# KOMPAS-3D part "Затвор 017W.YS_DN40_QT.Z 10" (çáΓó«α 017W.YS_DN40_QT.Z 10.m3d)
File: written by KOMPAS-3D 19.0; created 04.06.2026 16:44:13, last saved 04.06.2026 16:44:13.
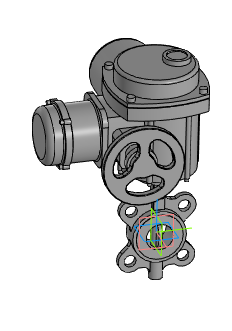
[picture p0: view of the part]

Document properties: Автор: Энергия; Полное имя файла: ..\..\..\3d для проектировщиков\017W разные\x.x Тип 017W.Y(S) Затвор дисковый поворотный межфланцевый\Привод\Привод QT.Z\Затвор 017W.YS_DN40_QT.Z 10.a3d

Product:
- Part/product: Затвор 017W.YS_DN40_QT.Z 10
    Масса: 29.5518

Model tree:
1. Операция без истории:1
